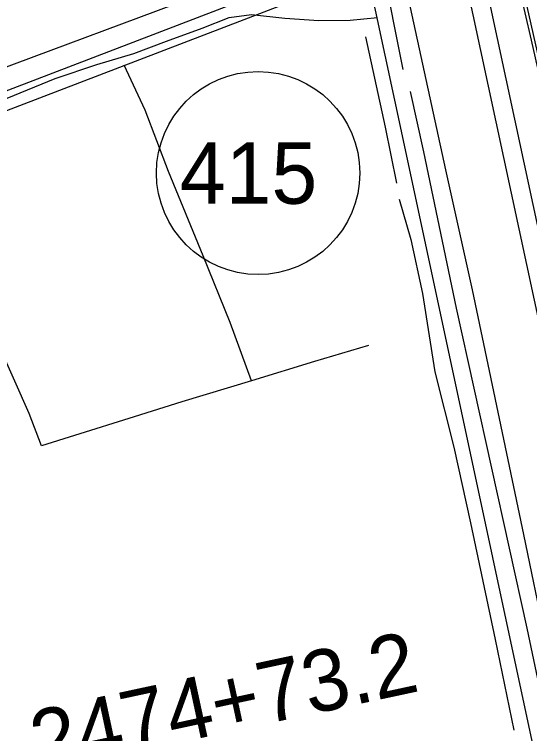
# Model space of a CAD drawing. Extents: x 3263578 to 3301413, y 764927 to 798602.
# Drawn here: x 3273815 to 3274651, y 791406 to 792575 of the extents above; entities that cross this region are included whole.
import ezdxf

# ---------------------------------------------------------------- set-up
doc = ezdxf.new("R2010")
doc.units = 0
for name, color, linetype in [('V-DTCH-CNTR', 7, 'Continuous'), ('V-LEVE-TOET', 7, 'Continuous'), ('V-ROAD-CNTR', 7, 'Continuous'), ('V-ROAD-IDEN', 7, 'Continuous'), ('V-SURV-IDEN', 7, 'Continuous'), ('V-SURV-LINE', 7, 'Continuous'), ('V-TOPO-SHOR', 7, 'Continuous')]:
    doc.layers.add(name, color=color, linetype=linetype)

msp = doc.modelspace()

# ---------------------------------------------------------------- linework, layer by layer
at = {"layer": 'V-DTCH-CNTR'}
msp.add_line((3274359.7, 792565.4), (3274404.3, 792570), dxfattribs=at)
msp.add_lwpolyline([(3273803.2, 792438.6), (3273881.2, 792470.4), (3273948.8, 792493.1), (3274008.9, 792511.1), (3274061.8, 792531.5), (3274119.5, 792552.3), (3274163.6, 792569.5), (3274199.7, 792574.4), (3274254, 792568.4), (3274308.9, 792565.1), (3274359.7, 792565.4)], dxfattribs=at)
at = {"layer": 'V-LEVE-TOET'}
for points in [[(3274147.7, 794016), (3274215.5, 793688.4), (3274292.5, 793337.8), (3274368.6, 792991.7), (3274440.3, 792665.9), (3274514.5, 792322.2), (3274557.9, 792127), (3274641.4, 791729.7), (3274711.5, 791389.4), (3274758.8, 791175.6), (3274817, 790903.8), (3274841.6, 790790.6), (3274847.2, 790760.6), (3274850.4, 790746), (3274855, 790725.6), (3274913.8, 790453.8), (3274977.1, 790147.8), (3275046.8, 789814.6)], [(3274973.8, 791123.4), (3274899.1, 791474.4), (3274828.9, 791780.6), (3274730.1, 792221.6), (3274640.7, 792616.7), (3274571.7, 792950.6), (3274481.8, 793386.4), (3274351.9, 793983.3), (3274344.6, 794016)]]:
    msp.add_lwpolyline(points, dxfattribs=at)
at = {"layer": 'V-ROAD-CNTR'}
for points in [[(3274094.3, 794018.7), (3274215.3, 793444.5), (3274447.4, 792362.4), (3274734.5, 791022), (3274976.4, 789891.9), (3275226.5, 788721.3)], [(3274331.5, 794015.5), (3274350.3, 793929.9), (3274380, 793805.9), (3274400.6, 793698.6), (3274418.3, 793593.2), (3274459.4, 793434.7), (3274489.9, 793313.8), (3274507.7, 793251.1), (3274517.2, 793208.4), (3274526, 793148), (3274544.1, 793045), (3274573, 792898.6), (3274612.8, 792711.2), (3274654, 792533.1), (3274745, 792128.2), (3274813.2, 791823.6), (3274860.3, 791605.2), (3274905.4, 791410.1), (3274927.3, 791268.6)], [(3274378.6, 792671.9), (3273707.6, 792414.1), (3273068.3, 792165.8)], [(3274389.4, 792643.9), (3273718.4, 792386.1), (3273079.2, 792137.8)]]:
    msp.add_lwpolyline(points, dxfattribs=at)
at = {"layer": 'V-ROAD-IDEN'}
msp.add_circle((3274210.5, 792317), 165, dxfattribs=at)
msp.add_circle((3274210.5, 792317), 165, dxfattribs=at)
at = {"layer": 'V-SURV-LINE'}
for points in [[(3274771.3, 791588.8), (3274250.3, 794016)], [(3274281, 794016), (3274800.6, 791595.1)]]:
    msp.add_lwpolyline(points, dxfattribs=at)
at = {"layer": 'V-TOPO-SHOR'}
msp.add_line((3273631.5, 792425.6), (3274309.6, 792679.5), dxfattribs=at)
for points in [[(3274446.1, 792485.4), (3274345.5, 792991), (3274319.2, 793113.2), (3274170.7, 793812.8)], [(3274385.1, 792538.1), (3274416.5, 792391.7), (3274435.3, 792300.6)], [(3274389.6, 792036.7), (3274301.8, 792010.5), (3274199.7, 791979), (3274164.9, 792074.3), (3274121.4, 792182.5), (3274065, 792319.2), (3274027, 792419.1), (3273993.1, 792492.2)], [(3274805.4, 790834.5), (3274757.5, 791052.6), (3274647.3, 791577.3), (3274532.4, 792097.2), (3274479.7, 792351.2), (3274458.1, 792449.5)], [(3274199.7, 791979), (3274086.7, 791944.9), (3274009.4, 791920.9), (3273912.3, 791890.5), (3273858.6, 791873.6), (3273838.6, 791926.4), (3273789.6, 792036.2), (3273747.8, 792135.8), (3273701.9, 792250.1), (3273658.5, 792356.2)], [(3274439.5, 792274.6), (3274458.5, 792208.7), (3274477.3, 792121.2), (3274497.6, 791994), (3274528, 791871.2), (3274555.3, 791748.3), (3274595.5, 791558.6), (3274625.4, 791411.6)]]:
    msp.add_lwpolyline(points, dxfattribs=at)

# ---------------------------------------------------------------- texts
at = {"layer": 'V-ROAD-IDEN'}
msp.add_text('415', height=100, rotation=360, dxfattribs=at).set_placement((3274083.4, 792267))
at = {"layer": 'V-SURV-IDEN'}
msp.add_text('2474+73.2', height=100, rotation=12.1483, dxfattribs=at).set_placement((3273853.9, 791341.9))

doc.saveas('drawing.dxf')
